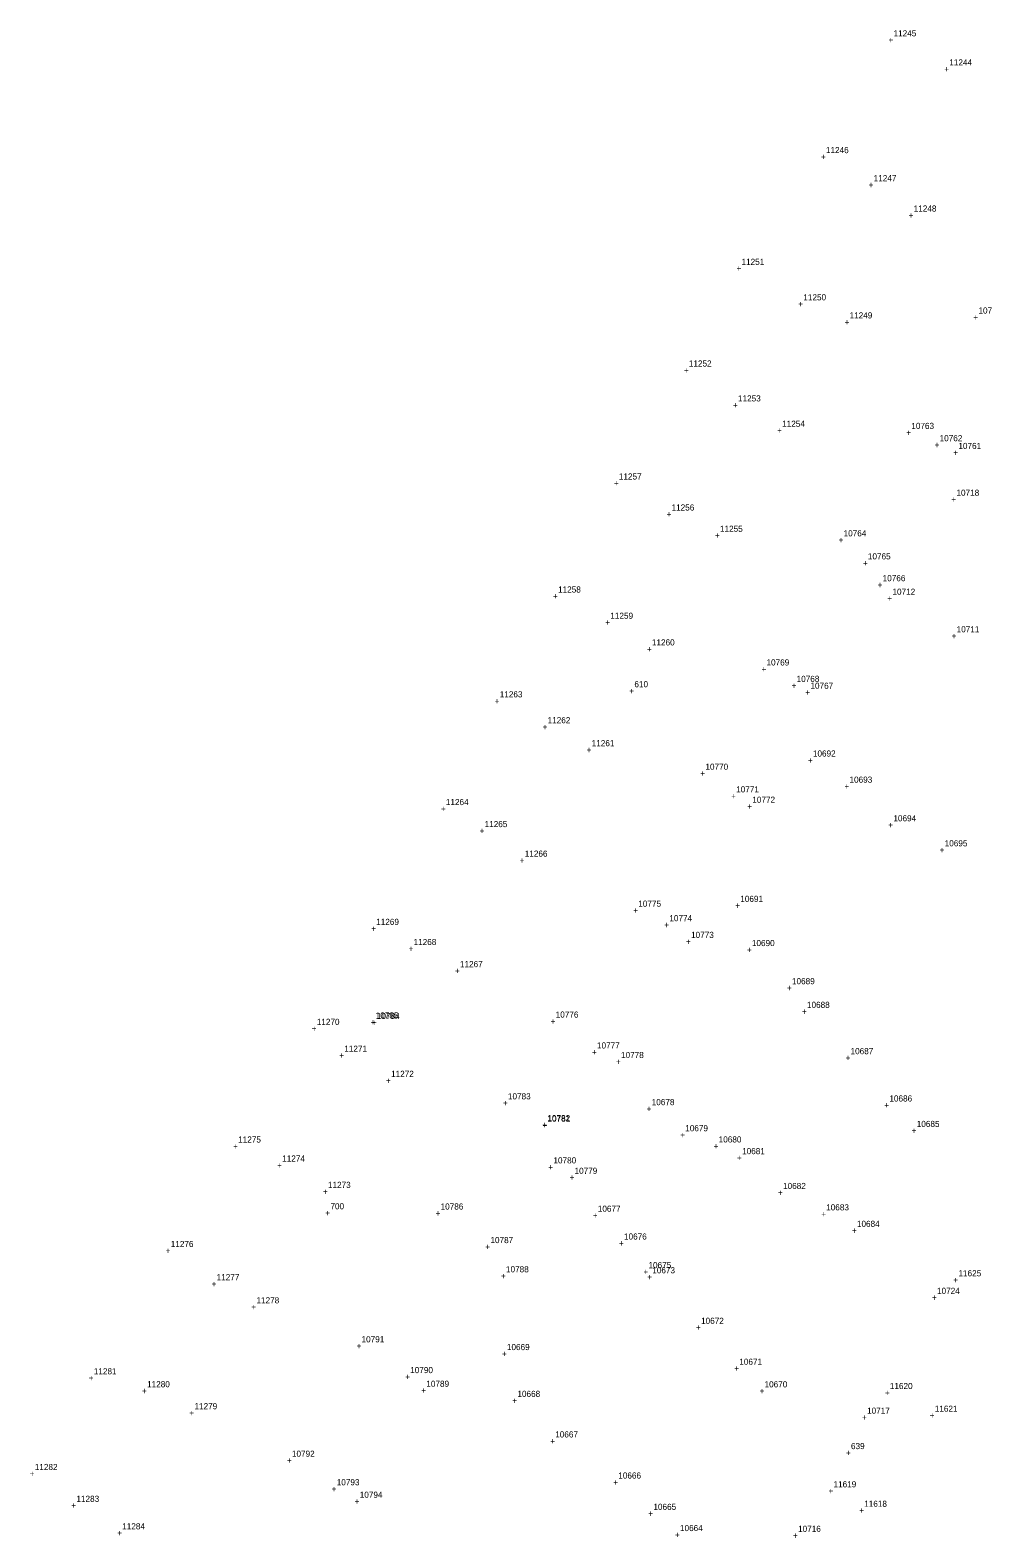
# Model space of a CAD drawing. Extents: x 1160051 to 1162814, y 614604 to 619560.
# Drawn here: x 1162124 to 1162513, y 618944 to 619560 of the extents above; entities that cross this region are included whole.
import ezdxf

# ---------------------------------------------------------------- set-up
doc = ezdxf.new("R2010")
doc.units = 0
for name, color, linetype in [('S_Control_Temp_Traverse', 7, 'Continuous'), ('S_Control_Traverse_Point', 7, 'Continuous'), ('S_Drainage_Culvert_Top', 7, 'Continuous'), ('S_Drainage_Invert', 7, 'Continuous'), ('S_Ground_Elevation', 7, 'Continuous'), ('S_Guardrail_Beam', 7, 'Continuous'), ('S_Trees_TreeLine', 7, 'Continuous')]:
    doc.layers.add(name, color=color, linetype=linetype)

msp = doc.modelspace()

# ---------------------------------------------------------------- texts
at = {"layer": 'S_Control_Temp_Traverse'}
for s, p in [('+', (1162368.41, 619288.89)), ('610', (1162370.47, 619291.64)), ('639', (1162458.95, 618980.58)), ('+', (1162456.89, 618977.83))]:
    msp.add_text(s, height=2.5, dxfattribs=at).set_placement(p)
at = {"layer": 'S_Control_Traverse_Point'}
for s, p in [('+', (1162244.25, 619075.75)), ('+', (1162244.25, 619075.75)), ('+', (1162244.25, 619075.75)), ('+', (1162244.25, 619075.75)), ('700', (1162246.31, 619078.5)), ('700', (1162246.31, 619078.5)), ('700', (1162246.31, 619078.5)), ('700', (1162246.31, 619078.5))]:
    msp.add_text(s, height=2.5, dxfattribs=at).set_placement(p)
at = {"layer": 'S_Drainage_Culvert_Top'}
for s, p in [('+', (1162263.2, 619153.45)), ('10784', (1162265.27, 619156.2)), ('+', (1162332.86, 619111.73)), ('10782', (1162334.93, 619114.48))]:
    msp.add_text(s, height=2.5, dxfattribs=at).set_placement(p)
at = {"layer": 'S_Drainage_Invert'}
for s, p in [('+', (1162262.74, 619153.64)), ('10785', (1162264.8, 619156.39)), ('+', (1162332.92, 619111.49)), ('10781', (1162334.98, 619114.24))]:
    msp.add_text(s, height=2.5, dxfattribs=at).set_placement(p)
at = {"layer": 'S_Ground_Elevation'}
for s, p in [('+', (1162474.27, 619554.63)), ('11245', (1162476.34, 619557.37)), ('+', (1162497.06, 619542.77)), ('11244', (1162499.12, 619545.52)), ('11246', (1162448.71, 619509.69)), ('+', (1162446.65, 619506.94)), ('11247', (1162468.22, 619498.23)), ('+', (1162466.16, 619495.48)), ('11248', (1162484.57, 619485.83)), ('+', (1162482.51, 619483.08)), ('+', (1162412.17, 619461.33)), ('11251', (1162414.23, 619464.08)), ('11250', (1162439.49, 619449.59)), ('+', (1162437.43, 619446.84)), ('11249', (1162458.37, 619442.21)), ('10758', (1162511.03, 619444.2)), ('+', (1162456.31, 619439.46)), ('+', (1162508.97, 619441.45)), ('+', (1162390.66, 619419.81)), ('11252', (1162392.72, 619422.56)), ('+', (1162410.74, 619405.57)), ('11253', (1162412.8, 619408.32)), ('+', (1162428.77, 619395.22)), ('11254', (1162430.83, 619397.97)), ('+', (1162481.53, 619394.34)), ('10763', (1162483.59, 619397.09)), ('+', (1162493.09, 619389.33)), ('10762', (1162495.15, 619392.08)), ('10761', (1162502.83, 619388.91)), ('+', (1162500.77, 619386.16)), ('11257', (1162364.12, 619376.44)), ('+', (1162362.06, 619373.69)), ('10718', (1162502.04, 619369.8)), ('11256', (1162385.65, 619363.78)), ('+', (1162499.98, 619367.05)), ('+', (1162383.59, 619361.03)), ('+', (1162403.36, 619352.34)), ('11255', (1162405.43, 619355.09)), ('+', (1162453.88, 619350.49)), ('10764', (1162455.94, 619353.24)), ('10765', (1162465.85, 619343.83)), ('+', (1162463.79, 619341.08)), ('+', (1162469.83, 619332.17)), ('10766', (1162471.89, 619334.92)), ('+', (1162337.23, 619327.56)), ('11258', (1162339.29, 619330.31)), ('+', (1162473.84, 619326.63)), ('10712', (1162475.9, 619329.38)), ('11259', (1162360.64, 619319.57)), ('+', (1162358.58, 619316.82)), ('10711', (1162502.11, 619314.07)), ('11260', (1162377.62, 619308.7)), ('+', (1162500.05, 619311.32)), ('+', (1162375.56, 619305.95)), ('10769', (1162424.44, 619300.52)), ('+', (1162422.38, 619297.77)), ('+', (1162434.68, 619291.06)), ('10768', (1162436.74, 619293.81)), ('10767', (1162442.39, 619291.02)), ('+', (1162313.4, 619284.75)), ('11263', (1162315.46, 619287.5)), ('+', (1162440.33, 619288.27)), ('11262', (1162335.02, 619276.94)), ('+', (1162332.96, 619274.19)), ('+', (1162350.97, 619264.81)), ('11261', (1162353.03, 619267.56)), ('10692', (1162443.39, 619263.33)), ('10770', (1162399.49, 619257.93)), ('+', (1162441.33, 619260.58)), ('+', (1162397.43, 619255.18)), ('10693', (1162458.35, 619252.67)), ('+', (1162409.98, 619245.96)), ('10771', (1162412.05, 619248.71)), ('+', (1162456.28, 619249.92)), ('+', (1162291.39, 619240.76)), ('11264', (1162293.45, 619243.51)), ('+', (1162416.58, 619241.72)), ('10772', (1162418.65, 619244.47)), ('11265', (1162309.29, 619234.52)), ('+', (1162474.22, 619234.14)), ('10694', (1162476.28, 619236.89)), ('+', (1162307.23, 619231.77)), ('10695', (1162497.23, 619226.67)), ('11266', (1162325.68, 619222.45)), ('+', (1162495.17, 619223.92)), ('+', (1162323.62, 619219.7)), ('10775', (1162372.06, 619202.04)), ('10691', (1162413.72, 619204)), ('+', (1162370, 619199.29)), ('10774', (1162384.76, 619196.11)), ('+', (1162411.66, 619201.25)), ('+', (1162262.94, 619191.85)), ('11269', (1162265, 619194.6)), ('+', (1162382.7, 619193.36)), ('11268', (1162280.27, 619186.38)), ('+', (1162391.56, 619186.53)), ('10773', (1162393.62, 619189.28)), ('10690', (1162418.47, 619185.95)), ('+', (1162278.21, 619183.63)), ('11267', (1162299.21, 619177.35)), ('+', (1162416.41, 619183.2)), ('+', (1162297.15, 619174.6)), ('10688', (1162440.97, 619160.73)), ('11270', (1162240.73, 619153.77)), ('+', (1162336.27, 619154)), ('10776', (1162338.33, 619156.75)), ('+', (1162438.91, 619157.98)), ('+', (1162238.67, 619151.02)), ('11271', (1162251.96, 619142.82)), ('+', (1162353.13, 619141.4)), ('10777', (1162355.19, 619144.15)), ('10778', (1162365.01, 619140.24)), ('10687', (1162458.77, 619141.82)), ('+', (1162249.9, 619140.07)), ('+', (1162362.95, 619137.49)), ('+', (1162456.71, 619139.07)), ('+', (1162269.01, 619129.79)), ('11272', (1162271.07, 619132.54)), ('10783', (1162318.81, 619123.38)), ('10686', (1162474.65, 619122.5)), ('+', (1162316.74, 619120.63)), ('+', (1162375.49, 619118.26)), ('10678', (1162377.55, 619121.01)), ('+', (1162472.59, 619119.75)), ('10679', (1162391.23, 619110.36)), ('10685', (1162485.82, 619112.1)), ('11275', (1162208.61, 619105.73)), ('+', (1162389.16, 619107.61)), ('+', (1162483.76, 619109.35)), ('+', (1162206.55, 619102.98)), ('11274', (1162226.59, 619097.98)), ('10780', (1162337.4, 619097.23)), ('+', (1162412.42, 619098.25)), ('10681', (1162414.48, 619101)), ('+', (1162224.52, 619095.23)), ('+', (1162335.34, 619094.48)), ('10779', (1162346.02, 619092.96)), ('11273', (1162245.29, 619087.21)), ('+', (1162343.96, 619090.21)), ('10682', (1162431.2, 619086.77)), ('+', (1162243.23, 619084.46)), ('+', (1162429.14, 619084.02)), ('+', (1162289.24, 619075.64)), ('10786', (1162291.3, 619078.39)), ('+', (1162353.47, 619074.73)), ('10677', (1162355.53, 619077.48)), ('+', (1162446.76, 619075.3)), ('10683', (1162448.82, 619078.05)), ('+', (1162459.31, 619068.56)), ('10684', (1162461.37, 619071.31)), ('11276', (1162181.07, 619063.08)), ('+', (1162309.61, 619061.94)), ('10787', (1162311.67, 619064.69)), ('+', (1162364.17, 619063.39)), ('10676', (1162366.23, 619066.14)), ('+', (1162179.01, 619060.33)), ('11277', (1162199.81, 619049.52)), ('+', (1162315.96, 619050.01)), ('10788', (1162318.02, 619052.76)), ('+', (1162375.71, 619049.62)), ('10673', (1162377.77, 619052.37)), ('+', (1162500.79, 619048.39)), ('11625', (1162502.85, 619051.14)), ('+', (1162197.74, 619046.77)), ('+', (1162214.03, 619037.34)), ('11278', (1162216.09, 619040.09)), ('10672', (1162397.71, 619031.73)), ('10791', (1162259.01, 619024.2)), ('+', (1162395.65, 619028.98)), ('+', (1162256.95, 619021.45)), ('+', (1162316.33, 619018.25)), ('10669', (1162318.39, 619021)), ('11281', (1162149.64, 619011.11)), ('10790', (1162278.89, 619011.61)), ('+', (1162411.26, 619012.26)), ('10671', (1162413.32, 619015.01)), ('+', (1162147.58, 619008.36)), ('11280', (1162171.41, 619005.85)), ('+', (1162276.83, 619008.86)), ('10789', (1162285.48, 619006.02)), ('10670', (1162423.64, 619005.81)), ('11620', (1162474.83, 619005.09)), ('+', (1162169.35, 619003.1)), ('+', (1162283.42, 619003.27)), ('+', (1162320.63, 618999.15)), ('10668', (1162322.69, 619001.9)), ('+', (1162421.58, 619003.06)), ('+', (1162472.77, 619002.34)), ('+', (1162188.7, 618994.11)), ('11279', (1162190.76, 618996.86)), ('+', (1162491.13, 618993.08)), ('11621', (1162493.19, 618995.83)), ('+', (1162336.07, 618982.59)), ('10667', (1162338.13, 618985.34)), ('+', (1162228.51, 618974.72)), ('10792', (1162230.57, 618977.47)), ('+', (1162123.47, 618969.29)), ('11282', (1162125.53, 618972.04)), ('10666', (1162363.89, 618968.56)), ('+', (1162246.81, 618963.07)), ('10793', (1162248.88, 618965.82)), ('+', (1162361.83, 618965.81)), ('+', (1162449.76, 618962.24)), ('11619', (1162451.82, 618964.99)), ('+', (1162140.48, 618956.31)), ('11283', (1162142.54, 618959.06)), ('+', (1162256.22, 618957.95)), ('10794', (1162258.28, 618960.7)), ('10665', (1162378.24, 618955.77)), ('11618', (1162464.35, 618957.02)), ('+', (1162376.18, 618953.02)), ('+', (1162462.29, 618954.27)), ('+', (1162159.18, 618945.08)), ('11284', (1162161.24, 618947.83)), ('+', (1162387.04, 618944.36)), ('10664', (1162389.1, 618947.11))]:
    msp.add_text(s, height=2.5, dxfattribs=at).set_placement(p)
at = {"layer": 'S_Guardrail_Beam'}
for s, p in [('10724', (1162494.1, 619043.96)), ('+', (1162492.04, 619041.21)), ('10717', (1162465.52, 618995.04)), ('+', (1162463.46, 618992.29)), ('+', (1162435.28, 618944.04)), ('10716', (1162437.34, 618946.79))]:
    msp.add_text(s, height=2.5, dxfattribs=at).set_placement(p)
at = {"layer": 'S_Trees_TreeLine'}
for s, p in [('+', (1162432.78, 619167.64)), ('10689', (1162434.84, 619170.39)), ('10680', (1162404.9, 619105.78)), ('+', (1162402.84, 619103.03)), ('10675', (1162376.23, 619054.45)), ('+', (1162374.17, 619051.7))]:
    msp.add_text(s, height=2.5, dxfattribs=at).set_placement(p)

doc.saveas('drawing.dxf')
